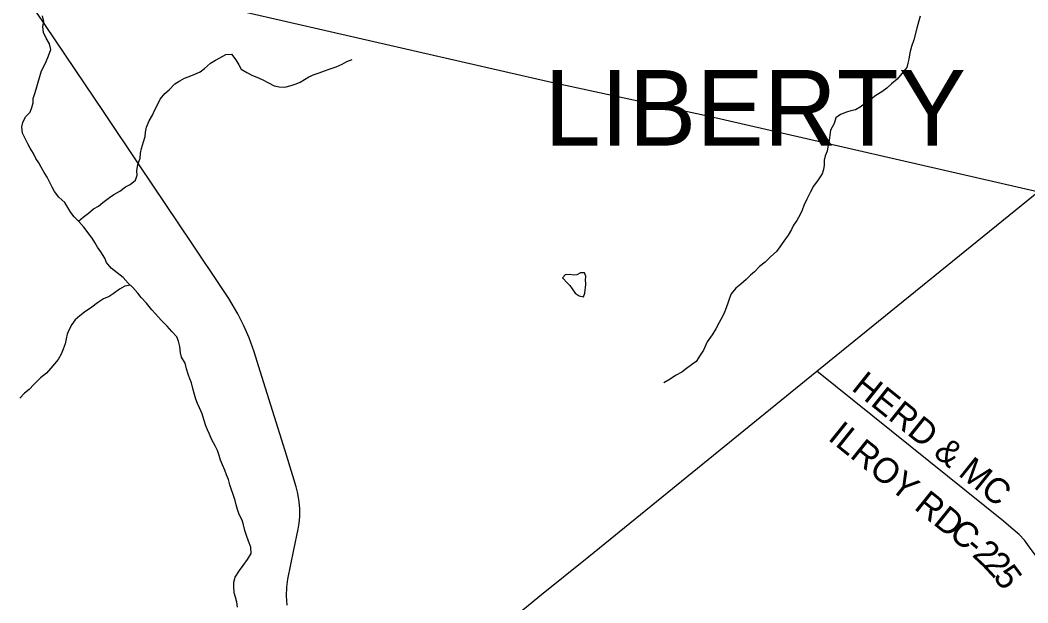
# Model space of a CAD drawing. Extents: x 0 to 34, y 0 to 22.
# Drawn here: x 3.154 to 4.289, y 15.083 to 15.74 of the extents above; entities that cross this region are included whole.
import ezdxf

# ---------------------------------------------------------------- set-up
doc = ezdxf.new("R2010")
doc.units = 0
for name, color, linetype in [('GM_X_County_Road', 7, 'Continuous'), ('GM_X_County_Road_Text', 7, 'Continuous'), ('GM_X_Minor_Lake', 7, 'Continuous'), ('GM_X_Minor_River', 7, 'Continuous'), ('GM_X_Rail_Line', 7, 'Continuous'), ('GM_X_State_Route', 7, 'Continuous'), ('GM_X_Township_Text', 7, 'Continuous')]:
    doc.layers.add(name, color=color, linetype=linetype)

msp = doc.modelspace()

# ---------------------------------------------------------------- linework, layer by layer
at = {"layer": 'GM_X_County_Road'}
for points in [[(3.4547, 15.0805), (3.454, 15.091), (3.4546, 15.1007), (3.4557, 15.1095), (3.4625, 15.1427), (3.4672, 15.166), (3.4684, 15.1729), (3.469, 15.1798), (3.4692, 15.1891), (3.4684, 15.1968), (3.4668, 15.2061), (3.4648, 15.2137), (3.4611, 15.2261), (3.4524, 15.2544), (3.4245, 15.3442), (3.4176, 15.3658), (3.412, 15.3815), (3.4061, 15.3952), (3.3991, 15.4088), (3.3891, 15.4259), (3.3823, 15.4363), (3.3468, 15.4893), (3.289, 15.5756), (3.2487, 15.6355), (3.1608, 15.7663)], [(4.306, 15.1259), (4.293, 15.1432), (4.2852, 15.1538), (4.2795, 15.1601), (4.2699, 15.1679), (4.2618, 15.1749), (4.0515, 15.344)]]:
    msp.add_lwpolyline(points, dxfattribs=at)
at = {"layer": 'GM_X_Minor_Lake'}
for points in [[(3.7911, 15.4433), (3.791, 15.4467), (3.7914, 15.4512), (3.7897, 15.455), (3.7854, 15.455), (3.7812, 15.4528), (3.7772, 15.4524), (3.7731, 15.4532), (3.7681, 15.4526), (3.7649, 15.4494)], [(3.7649, 15.4494), (3.7707, 15.4433), (3.7734, 15.4405), (3.776, 15.4367), (3.7794, 15.4321), (3.7836, 15.4291), (3.7885, 15.4277), (3.79, 15.4319), (3.7912, 15.4417), (3.7911, 15.4433)]]:
    msp.add_lwpolyline(points, dxfattribs=at)
at = {"layer": 'GM_X_Minor_River'}
for points in [[(3.2045, 15.534), (3.1975, 15.5403), (3.1928, 15.5464), (3.1902, 15.5516), (3.1846, 15.5626), (3.181, 15.5681), (3.1778, 15.574), (3.1752, 15.5787), (3.1718, 15.5837), (3.169, 15.5894), (3.1652, 15.5953), (3.1626, 15.6002), (3.16, 15.6054), (3.1568, 15.6124), (3.1561, 15.6194), (3.1572, 15.6243), (3.1599, 15.6306), (3.1653, 15.6359), (3.1674, 15.6412), (3.1687, 15.6466), (3.1689, 15.6514), (3.1709, 15.6582), (3.173, 15.6646), (3.1745, 15.6697), (3.1761, 15.676), (3.1782, 15.6824), (3.1809, 15.6873), (3.1832, 15.693), (3.1861, 15.6996), (3.1887, 15.7066), (3.1871, 15.7129), (3.1835, 15.7192), (3.1803, 15.7256), (3.1796, 15.7325), (3.1808, 15.7381), (3.1793, 15.7444)], [(4.1678, 15.7443), (4.1663, 15.739), (4.164, 15.7305), (4.1607, 15.7176), (4.158, 15.7099), (4.1563, 15.703), (4.1549, 15.6958), (4.154, 15.6911), (4.1528, 15.6864), (4.1473, 15.6797), (4.1418, 15.6733), (4.1357, 15.668), (4.1304, 15.6629), (4.1247, 15.6589), (4.118, 15.6546), (4.1131, 15.651), (4.1063, 15.6463), (4.1015, 15.6425), (4.0949, 15.6386), (4.0896, 15.6376), (4.0848, 15.6361), (4.0782, 15.6335), (4.0729, 15.6295), (4.0708, 15.6233), (4.0669, 15.6157), (4.066, 15.6102), (4.0652, 15.6042), (4.0638, 15.5969), (4.0629, 15.592), (4.061, 15.5867), (4.0598, 15.582), (4.0596, 15.5761), (4.0588, 15.5714), (4.0573, 15.5666), (4.0529, 15.5596), (4.0476, 15.5526), (4.044, 15.5456), (4.04, 15.5378), (4.0369, 15.5306), (4.035, 15.5257), (4.0327, 15.5206), (4.0291, 15.5138), (4.0253, 15.5087), (4.0228, 15.5037), (4.019, 15.4973), (4.0142, 15.4905), (4.0099, 15.4843), (4.0059, 15.479), (3.9998, 15.4733), (3.9931, 15.467), (3.9867, 15.4619), (3.9813, 15.4559), (3.9766, 15.4523), (3.9717, 15.4474), (3.9658, 15.4421), (3.9603, 15.4378), (3.9551, 15.4313), (3.9532, 15.4264), (3.9517, 15.4217), (3.9492, 15.4154), (3.9475, 15.4107), (3.9452, 15.4056), (3.9416, 15.3989), (3.9376, 15.3917), (3.9334, 15.3851), (3.9281, 15.3773)], [(3.2199, 15.5132), (3.2251, 15.5178), (3.2312, 15.522), (3.2367, 15.527), (3.2422, 15.5299), (3.2471, 15.534), (3.2546, 15.5397), (3.2597, 15.543), (3.2663, 15.547), (3.2728, 15.5517), (3.2778, 15.5543), (3.284, 15.5592), (3.286, 15.5651), (3.2856, 15.57), (3.2868, 15.577), (3.2891, 15.5842), (3.2895, 15.5899), (3.2907, 15.595), (3.293, 15.6024), (3.2947, 15.6087), (3.2953, 15.6136), (3.2965, 15.6191), (3.2993, 15.6261), (3.303, 15.6327), (3.3053, 15.6378), (3.3083, 15.6435), (3.3118, 15.6505), (3.3171, 15.6571), (3.3219, 15.661), (3.3284, 15.6678), (3.3341, 15.6714), (3.3392, 15.6744), (3.3443, 15.6763), (3.351, 15.6789), (3.3567, 15.6813), (3.3618, 15.6853), (3.3685, 15.6913), (3.3742, 15.6947), (3.3791, 15.6973), (3.3856, 15.7011), (3.392, 15.7012), (3.3969, 15.6951), (3.4003, 15.6894), (3.4031, 15.6845), (3.4093, 15.6807), (3.4157, 15.6772), (3.4207, 15.6755), (3.4267, 15.6726), (3.4337, 15.669), (3.4403, 15.6657), (3.4458, 15.6646), (3.4521, 15.6643), (3.4595, 15.6662), (3.4648, 15.6679), (3.4695, 15.6699), (3.4745, 15.6729), (3.4794, 15.6758), (3.4853, 15.6784), (3.491, 15.6803), (3.4969, 15.6825), (3.5031, 15.6847), (3.5102, 15.6872), (3.5166, 15.69), (3.5221, 15.6932), (3.5282, 15.6952)], [(3.3989, 15.0781), (3.398, 15.0838), (3.3965, 15.0893), (3.3952, 15.0943), (3.3947, 15.1013), (3.3947, 15.1062), (3.3962, 15.1119), (3.4012, 15.1195), (3.4052, 15.1249), (3.4102, 15.1319), (3.4144, 15.1387), (3.4138, 15.1458), (3.4114, 15.1524), (3.409, 15.1589), (3.4073, 15.1644), (3.4056, 15.171), (3.4041, 15.1762), (3.4006, 15.1826), (3.3987, 15.1881), (3.3974, 15.1933), (3.3963, 15.1984), (3.3939, 15.2052), (3.3916, 15.2113), (3.3901, 15.216), (3.3886, 15.2219), (3.3864, 15.2274), (3.3845, 15.2326), (3.3819, 15.2387), (3.3798, 15.2436), (3.3784, 15.2491), (3.3763, 15.2546), (3.3739, 15.2601), (3.3701, 15.2668), (3.3675, 15.2729), (3.365, 15.2778), (3.3632, 15.2826), (3.3609, 15.2896), (3.3591, 15.2959), (3.3559, 15.3027), (3.354, 15.3078), (3.3521, 15.3126), (3.3505, 15.3179), (3.3486, 15.3245), (3.3469, 15.3308), (3.345, 15.3356), (3.3432, 15.3407), (3.3413, 15.3466), (3.34, 15.353), (3.3359, 15.3597), (3.3346, 15.3646), (3.3339, 15.3718), (3.3324, 15.3779), (3.3307, 15.3827), (3.325, 15.3889), (3.3196, 15.3947), (3.313, 15.4017), (3.3064, 15.4086), (3.3024, 15.4133), (3.2964, 15.4208), (3.2904, 15.4272), (3.2866, 15.432), (3.2808, 15.4385), (3.2759, 15.4434), (3.27, 15.4495), (3.2634, 15.4549), (3.2566, 15.4602), (3.2515, 15.4665), (3.2495, 15.4714), (3.2448, 15.4785), (3.241, 15.4838), (3.2382, 15.4889), (3.2352, 15.4941), (3.2258, 15.5062), (3.2201, 15.5129), (3.215, 15.5179), (3.2111, 15.523), (3.2079, 15.5285), (3.2045, 15.534)], [(3.2783, 15.4409), (3.2721, 15.4398), (3.2658, 15.4366), (3.2589, 15.4314), (3.2542, 15.4284), (3.2481, 15.4256), (3.2413, 15.4212), (3.2348, 15.4163), (3.2266, 15.4105), (3.2213, 15.4065), (3.2162, 15.4018), (3.2122, 15.3967), (3.2091, 15.3912), (3.207, 15.3858), (3.2058, 15.3804), (3.2047, 15.375), (3.2025, 15.3689), (3.2001, 15.3632), (3.1968, 15.3572), (3.1928, 15.3523), (3.1886, 15.3474), (3.1838, 15.3419), (3.1768, 15.3366), (3.1694, 15.3291), (3.1642, 15.3234), (3.1589, 15.3191), (3.1538, 15.3136)], [(3.9281, 15.3773), (3.9237, 15.3677), (3.92, 15.362), (3.9154, 15.355), (3.9103, 15.3512), (3.9046, 15.3471), (3.8993, 15.3431), (3.8924, 15.3392), (3.8862, 15.335), (3.8791, 15.3311)]]:
    msp.add_lwpolyline(points, dxfattribs=at)
at = {"layer": 'GM_X_Rail_Line'}
msp.add_lwpolyline([(2.8725, 15.857), (2.9115, 15.8579), (2.9613, 15.8516), (2.9946, 15.8445), (3.2081, 15.795), (3.7492, 15.6705), (3.9302, 15.6314), (4.3, 15.5466), (4.6063, 15.4754), (4.9134, 15.4063), (4.9924, 15.381), (5.0264, 15.3654), (5.0626, 15.3427), (5.087, 15.3222), (5.1229, 15.2868)], dxfattribs=at)
at = {"layer": 'GM_X_State_Route'}
msp.add_lwpolyline([(3.5274, 14.752), (3.5627, 14.8175), (3.5752, 14.841), (3.5839, 14.8554), (3.6777, 15.0303), (3.6875, 15.0456), (3.6987, 15.0573), (3.7393, 15.091), (3.7947, 15.1352), (4.0515, 15.344), (4.484, 15.6949), (4.65, 15.8296)], dxfattribs=at)

# ---------------------------------------------------------------- texts
at = {"layer": 'GM_X_County_Road_Text'}
for s, height, rotation, p in [('HERD & MC', 0.02841, 321.3212, (4.0893, 15.3236)), ('ILROY RD', 0.02841, 321.2038, (4.0628, 15.2675)), ('C', 0.0284, 320.4228, (4.1989, 15.1584)), ('-', 0.0284, 319.5308, (4.2168, 15.1436)), ('2', 0.0284, 316.9912, (4.2254, 15.1362)), ('2', 0.0284, 312.9132, (4.2378, 15.1247)), ('5', 0.0284, 306.3901, (4.2492, 15.1125))]:
    msp.add_text(s, height=height, rotation=rotation, dxfattribs=at).set_placement(p)
at = {"layer": 'GM_X_Township_Text'}
msp.add_text('LIBERTY', height=0.08523, rotation=0, dxfattribs=at).set_placement((3.7445, 15.5983))

doc.saveas('drawing.dxf')
